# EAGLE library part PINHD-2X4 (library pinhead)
PIN HEADER
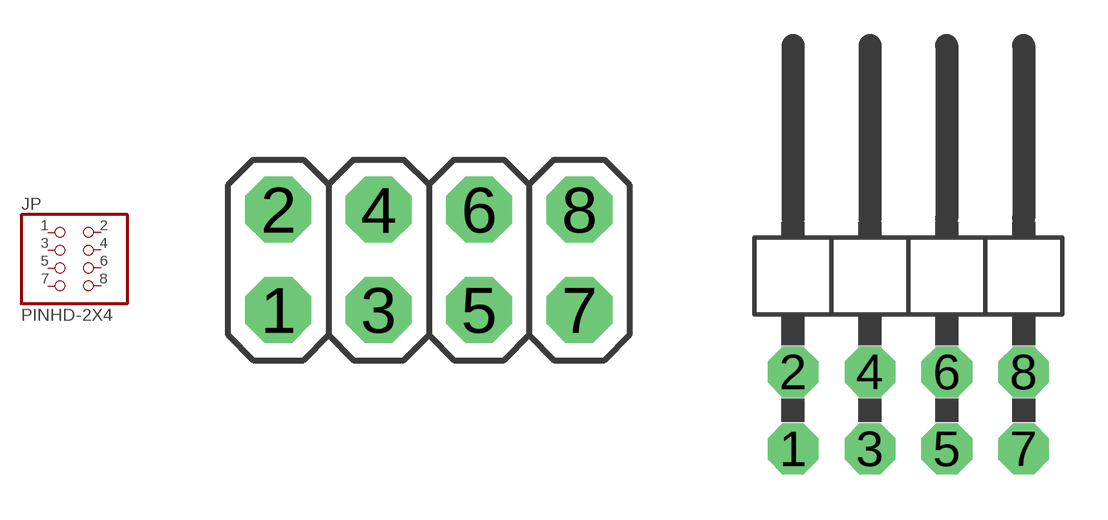
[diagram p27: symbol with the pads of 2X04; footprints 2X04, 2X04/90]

Designator prefix JP

## PINHD-2X4  [2X04]
1  1  pas
2  2  pas
3  3  pas
4  4  pas
5  5  pas
6  6  pas
7  7  pas
8  8  pas

## PINHD-2X4/90  [2X04/90]
Pads as for 2X04

## Footprint 2X04 (pad centres in mm)
PIN HEADER
drill 1.016 pad 1.67 octagon: 1 -3.81,-1.27; 2 -3.81,1.27; 3 -1.27,-1.27; 4 -1.27,1.27; 5 1.27,-1.27; 6 1.27,1.27; 7 3.81,-1.27; 8 3.81,1.27

## Footprint 2X04/90 (pad centres in mm)
PIN HEADER
drill 1.016 pad 1.67 octagon: 1 -3.81,-6.35; 2 -3.81,-3.81; 3 -1.27,-6.35; 4 -1.27,-3.81; 5 1.27,-6.35; 6 1.27,-3.81; 7 3.81,-6.35; 8 3.81,-3.81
